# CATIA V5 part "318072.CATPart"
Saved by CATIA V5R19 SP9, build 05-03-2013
Part number: 318072
Source: Unknown
Bounding box of the stored display mesh (mm): x -177.21 to -16.958, y -224.995 to -186.198, z 466.826 to 488.593
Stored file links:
  D:\16-SIL\kale oto\R19_V2\318072.CATPart
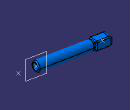
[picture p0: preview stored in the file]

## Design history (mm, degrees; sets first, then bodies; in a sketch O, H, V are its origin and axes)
Set1
  Point1 to Point3: stored without definition
  Plane1: type OffsetPt, RefPlane Plane2, RefPoint Point3
  Plane2: stored without definition
Body1 "241\\233\\231\\MANIFOLD_SOLID_BREP #158715" (main body)
  Solid1: solid without history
